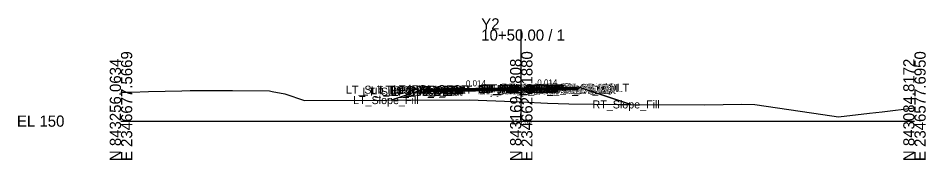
# Model space of a CAD drawing. Extents: x -26 to 2346977, y -10 to 843253.
# Drawn here: x -25.7 to 201.1, y -9.7 to 25.8 of the extents above; entities that cross this region are included whole.
import ezdxf

# ---------------------------------------------------------------- set-up
doc = ezdxf.new("R2010")
doc.units = 0
for name, color, linetype in [('Default', 7, 'Continuous'), ('Exist Cross Section Cell', 7, 'Continuous'), ('Exist XS Center Line Elevation Label', 7, 'Continuous'), ('Exist XS Ground Line', 7, 'Continuous'), ('Prop CMT Pvmt Course 1', 7, 'Continuous'), ('Prop CMT Pvmt Course 2', 7, 'Continuous'), ('Prop CMT Pvmt Course 3', 7, 'Continuous'), ('Prop CMT Pvmt Surface', 7, 'Continuous'), ('Prop CMT Pvmt Surface Shoulder', 7, 'Continuous'), ('Prop CMT Shld Paved Course 1', 7, 'Continuous'), ('Prop CMT Shld Paved Course 2', 7, 'Continuous'), ('Prop CMT Shld Paved Course 3', 7, 'Continuous'), ('Prop CMT Slope Grass', 7, 'Continuous'), ('Prop CMT Subgrade Earthwork', 7, 'Continuous'), ('Prop XS Earthwork Shape', 7, 'Continuous'), ('Prop XS SE Text', 7, 'Continuous'), ('Prop XS Side Slope Text', 7, 'Continuous'), ('Scratch_Level_2', 7, 'Continuous')]:
    doc.layers.add(name, color=color, linetype=linetype)

msp = doc.modelspace()

# ---------------------------------------------------------------- linework, layer by layer
at = {"layer": 'Exist Cross Section Cell'}
for p, q in [((100, 0), (100, 22.92)), ((0, 0), (100, 0)), ((100, 0), (198.24, 0))]:
    msp.add_line(p, q, dxfattribs=at)
at = {"layer": 'Exist XS Ground Line'}
msp.add_lwpolyline([(0, 7.23), (2.63, 7.27), (6.88, 7.38), (15.19, 7.57), (17.25, 7.62), (18.46, 7.64), (27.87, 7.62), (37.08, 7.6), (37.77, 7.42), (40.95, 6.81), (45.84, 5.13), (87.04, 5.36), (97.99, 4.92), (100, 4.83), (106.56, 4.52), (111.86, 4.32), (124.65, 4.18), (145.74, 4.09), (155.14, 4.25), (158.36, 4.16), (175.31, 1.64), (179.27, 1.11), (187.03, 1.95), (190.13, 2.29), (198.24, 3.33)], dxfattribs=at)
at = {"layer": 'Prop CMT Pvmt Course 1'}
for p, q in [((100, 8.3), (77.21, 7.99)), ((77.21, 7.74), (100, 8.05)), ((77.21, 7.99), (77.21, 7.74)), ((100, 8.3), (112.9, 8.47)), ((100, 8.05), (100, 8.3)), ((100, 8.05), (100, 8.3)), ((112.9, 8.22), (100, 8.05)), ((100, 8.05), (100, 8.17)), ((100, 8.17), (100, 8.17)), ((100, 8.17), (100, 8.05)), ((100, 8.05), (100, 8.17)), ((100, 8.17), (100, 8.17)), ((100, 8.17), (100, 8.05)), ((100, 8.05), (100, 8.05)), ((100, 8.05), (100, 8.05)), ((112.9, 8.47), (112.9, 8.22))]:
    msp.add_line(p, q, dxfattribs=at)
at = {"layer": 'Prop CMT Pvmt Course 2'}
for p, q in [((77.21, 7.74), (100, 8.05)), ((100, 8.05), (77.21, 7.74)), ((77.21, 7.74), (77.21, 7.74)), ((112.9, 8.22), (100, 8.05)), ((100, 8.05), (112.9, 8.22)), ((100, 8.05), (100, 8.05)), ((100, 8.05), (100, 8.05)), ((112.9, 8.22), (112.9, 8.22))]:
    msp.add_line(p, q, dxfattribs=at)
at = {"layer": 'Prop CMT Pvmt Course 3'}
for p, q in [((100, 8.05), (77.21, 7.74)), ((77.21, 7.74), (77.21, 7.4)), ((77.21, 7.4), (100, 7.71)), ((100, 8.05), (112.9, 8.22)), ((100, 7.71), (100, 8.05)), ((100, 7.71), (100, 8.05)), ((112.9, 7.89), (100, 7.71)), ((112.9, 8.22), (112.9, 7.89))]:
    msp.add_line(p, q, dxfattribs=at)
at = {"layer": 'Prop CMT Pvmt Surface'}
for q in [(77.21, 7.99), (112.9, 8.47)]:
    msp.add_line((100, 8.3), q, dxfattribs=at)
at = {"layer": 'Prop CMT Pvmt Surface Shoulder'}
for p, q in [((77.21, 7.99), (77.21, 7.99)), ((112.9, 8.47), (112.9, 8.47))]:
    msp.add_line(p, q, dxfattribs=at)
at = {"layer": 'Prop CMT Shld Paved Course 1'}
for p, q in [((77.21, 7.99), (76.96, 7.73)), ((76.96, 7.73), (77.21, 7.74)), ((77.21, 7.99), (77.21, 7.99)), ((77.21, 7.74), (77.21, 7.99)), ((112.9, 8.47), (112.9, 8.47)), ((112.9, 8.47), (113.15, 8.22)), ((112.9, 8.22), (112.9, 8.47)), ((113.15, 8.22), (112.9, 8.22))]:
    msp.add_line(p, q, dxfattribs=at)
at = {"layer": 'Prop CMT Shld Paved Course 2'}
for p, q in [((77.21, 7.74), (76.96, 7.73)), ((76.96, 7.73), (77.21, 7.74)), ((76.96, 7.73), (76.96, 7.73)), ((77.21, 7.74), (77.21, 7.74)), ((112.9, 8.22), (113.15, 8.22)), ((113.15, 8.22), (112.9, 8.22)), ((112.9, 8.22), (112.9, 8.22)), ((113.15, 8.22), (113.15, 8.22))]:
    msp.add_line(p, q, dxfattribs=at)
at = {"layer": 'Prop CMT Shld Paved Course 3'}
for p, q in [((76.46, 7.72), (76.12, 7.38)), ((76.12, 7.38), (77.21, 7.4)), ((76.96, 7.73), (76.46, 7.72)), ((77.21, 7.74), (76.96, 7.73)), ((77.21, 7.4), (77.21, 7.74)), ((112.9, 8.22), (113.15, 8.22)), ((112.9, 7.89), (112.9, 8.22)), ((113.99, 7.87), (112.9, 7.89)), ((113.15, 8.22), (113.65, 8.21)), ((113.65, 8.21), (113.99, 7.87))]:
    msp.add_line(p, q, dxfattribs=at)
at = {"layer": 'Prop CMT Slope Grass'}
for p, q in [((75.21, 7.83), (67.48, 5.25)), ((77.21, 7.99), (75.21, 7.83)), ((112.9, 8.47), (114.9, 8.31)), ((114.9, 8.31), (127.34, 4.17))]:
    msp.add_line(p, q, dxfattribs=at)
at = {"layer": 'Prop CMT Subgrade Earthwork'}
for p, q in [((76.12, 7.38), (75.64, 7.86)), ((77.21, 7.4), (76.12, 7.38)), ((100, 7.71), (77.21, 7.4)), ((100, 7.71), (112.9, 7.89)), ((112.9, 7.89), (113.99, 7.87)), ((113.99, 7.87), (114.47, 8.35))]:
    msp.add_line(p, q, dxfattribs=at)
at = {"layer": 'Prop XS Earthwork Shape'}
msp.add_lwpolyline([(67.48, 5.25), (87.04, 5.36), (97.99, 4.92), (100, 4.83), (106.56, 4.52), (111.86, 4.32), (124.65, 4.18), (127.34, 4.17), (114.9, 8.31), (114.47, 8.35), (113.99, 7.87), (112.9, 7.89), (100, 7.71), (77.21, 7.4), (76.12, 7.38), (75.64, 7.86), (75.21, 7.83)], close=True, dxfattribs=at)

# ---------------------------------------------------------------- texts
at = {"layer": 'Default'}
msp.add_text('-', height=0.0001, dxfattribs=at).set_placement((0, 0))
at = {"layer": 'Exist Cross Section Cell'}
for s, p in [('Y2', (90, 22.92)), ('10+50.00 / 1', (90, 20.12)), ('EL 150', (-26, -1.4))]:
    msp.add_text(s, height=2.8, dxfattribs=at).set_placement(p)
for s, p in [('E 2346677.5669', (2.8, -10)), ('E 2346627.1880', (102.8, -10)), ('E 2346577.6950', (201.04, -10)), ('N 843256.0634', (0, -10)), ('N 843169.6808', (100, -10)), ('N 843084.8172', (198.24, -10))]:
    msp.add_text(s, height=2.8, rotation=90, dxfattribs=at).set_placement(p)
at = {"layer": 'Exist XS Center Line Elevation Label'}
msp.add_text('154.83', height=1.2, dxfattribs=at).set_placement((97.55, -0.77))
at = {"layer": 'Prop XS SE Text'}
for p in [(86.18, 8.69), (104.02, 8.9)]:
    msp.add_text('0.014', height=1.5, rotation=0.7798, dxfattribs=at).set_placement(p)
at = {"layer": 'Prop XS Side Slope Text'}
for rotation, p in [(18.4332, (70.48, 6.96)), (341.5668, (119.76, 7.4))]:
    msp.add_text('3:1', height=1.5, rotation=rotation, dxfattribs=at).set_placement(p)
at = {"layer": 'Scratch_Level_2'}
for s, p in [('RT_PV2_OEEOP', (89.26, 7.05)), ('RT_PV3_OEEOP', (89.26, 7.05)), ('LT_PV2_OEEOP', (89.31, 7.05)), ('LT_PV3_OEEOP', (89.31, 7.05)), ('RT_PV1_OEEOP', (89.83, 7.17)), ('LT_PV1_OEEOP', (89.87, 7.17)), ('RT_PV2_IEEOP', (89.91, 7.05)), ('LT_PV2_IEEOP', (89.95, 7.05)), ('RT_PV1_IEEOP', (90.47, 7.17)), ('LT_PV1_IEEOP', (90.52, 7.17)), ('PV2_PGL', (93.91, 7.05)), ('PV1_PGL', (94.47, 7.3)), ('RT_Sub_Trench_Out_DLT', (94.99, 7.35)), ('RT_PS3_Shelf_Out', (99.59, 7.21)), ('RT_PV3_OEOT', (103.02, 7.22)), ('RT_PV2_OEOT', (103.02, 7.22)), ('RT_PS3_OEOP', (103.34, 7.22)), ('RT_PS2_OEOP', (103.34, 7.22)), ('RT_PV1_OEOT', (103.59, 7.47)), ('RT_PS1_OEOP', (103.65, 7.47)), ('RT_GS_OS_CTL', (104.22, 7.31)), ('LT_Sub_Trench_Out_DLT', (56.2, 6.86)), ('LT_Sub_Trench_Out', (60.32, 6.38)), ('LT_PS3_Shelf_Out', (62.44, 6.72)), ('LT_GS_OS_CTL', (64.58, 6.83)), ('LT_PS3_OEOP', (67.19, 6.73)), ('LT_PS2_OEOP', (67.19, 6.73)), ('LT_Sub_OEOT', (67.29, 6.4)), ('LT_PV3_OEOT', (67.38, 6.74)), ('LT_PV2_OEOT', (67.38, 6.74)), ('LT_PV1_OEOT', (67.95, 6.99)), ('LT_PS1_OEOP', (68.01, 6.99)), ('RT_Sub_OEEOP', (89.17, 6.71)), ('LT_Sub_OEEOP', (89.21, 6.71)), ('RT_Sub_Trench_Out', (98.15, 6.87)), ('RT_Sub_OEOT', (102.93, 6.89)), ('LT_Slope_Fill', (58, 4.25)), ('RT_Slope_Fill', (117.81, 3.17))]:
    msp.add_text(s, height=2, dxfattribs=at).set_placement(p)

doc.saveas('drawing.dxf')
